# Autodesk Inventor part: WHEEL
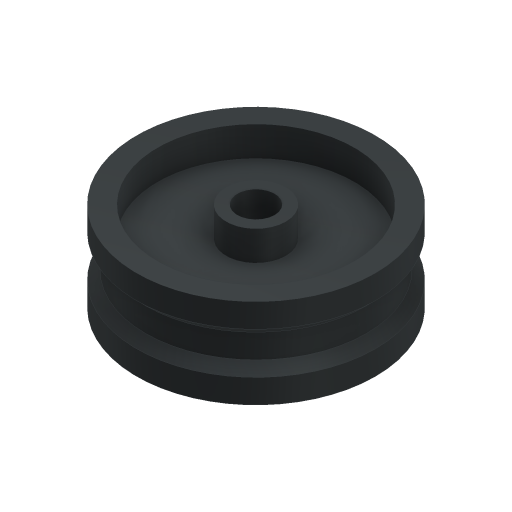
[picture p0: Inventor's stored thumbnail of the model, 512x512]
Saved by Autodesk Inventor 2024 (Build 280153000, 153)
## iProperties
Created: 2016-05
Part Number: WHEEL
Material: Iron, Cast
Document SubType Name: Modeling
Designer: CADCIM
Density: 7.15 g/cm^3
Appearance: Iron Gray
Mass: 68.7858 g
Surface Area: 60.8074 cm^2
Volume: 9.62039 cm^3
Author: CADCIM
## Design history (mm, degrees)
sketch "Sketch1"
  geometry: L1 (0, 0)-(-43, 0); L2 (-20, 3.5)-(-18.5, 2); L3 (-20, -3.5)-(-18.5, -2); L4 (-20, 7.5)-(-20, 3.5); L5 (-20, -3.5)-(-20, -7.5); L6 (-5, 7.5)-(-5, 2.5); L7 (-5, 2.5)-(-16.5, 2.5); L8 (-16.5, 2.5)-(-16.5, 7.5); L9 (-16.5, -7.5)-(-16.5, -2.5); L10 (-16.5, -2.5)-(-5, -2.5); L11 (-5, -2.5)-(-5, -7.5); L12 (-3.125, 7.5)-(-5, 7.5); L13 (-16.5, 7.5)-(-20, 7.5); L14 (-20, -7.5)-(-16.5, -7.5); L15 (-5, -7.5)-(-3.125, -7.5); L16 (0, 7.495)-(0, -7.5); L17 (-3.125, 7.5)-(-3.125, -7.5); L18 (-18.5, 2)-(-18.5, -2); 1 further point
  constraints: 36 end point, 11 perpendicular, 4 collinear, 4 parallel, 4 vertical, 3 horizontal, 2 point on line, 4 other
  dimensions: "d1" = 15 distance of L4.start L5.end; "d2" = 90 deg angle of L3 L2; "d3" = 4 distance of L2.start L4.start; "d4" = 5 distance between parallel lines of L10 L7; "d5" = 6.25 diameter of L17 L16; "d6" = 10 diameter of L11 L16; "d7" = 33 diameter of L9 L16; "d9" = 40 diameter of L4 L16; "d11" = 1.5 distance between parallel lines of L5 L18
revolve "Revolution1" sketch "Sketch1" stored, may be unused: angle "d10" = 90 deg
body "Solid1"
